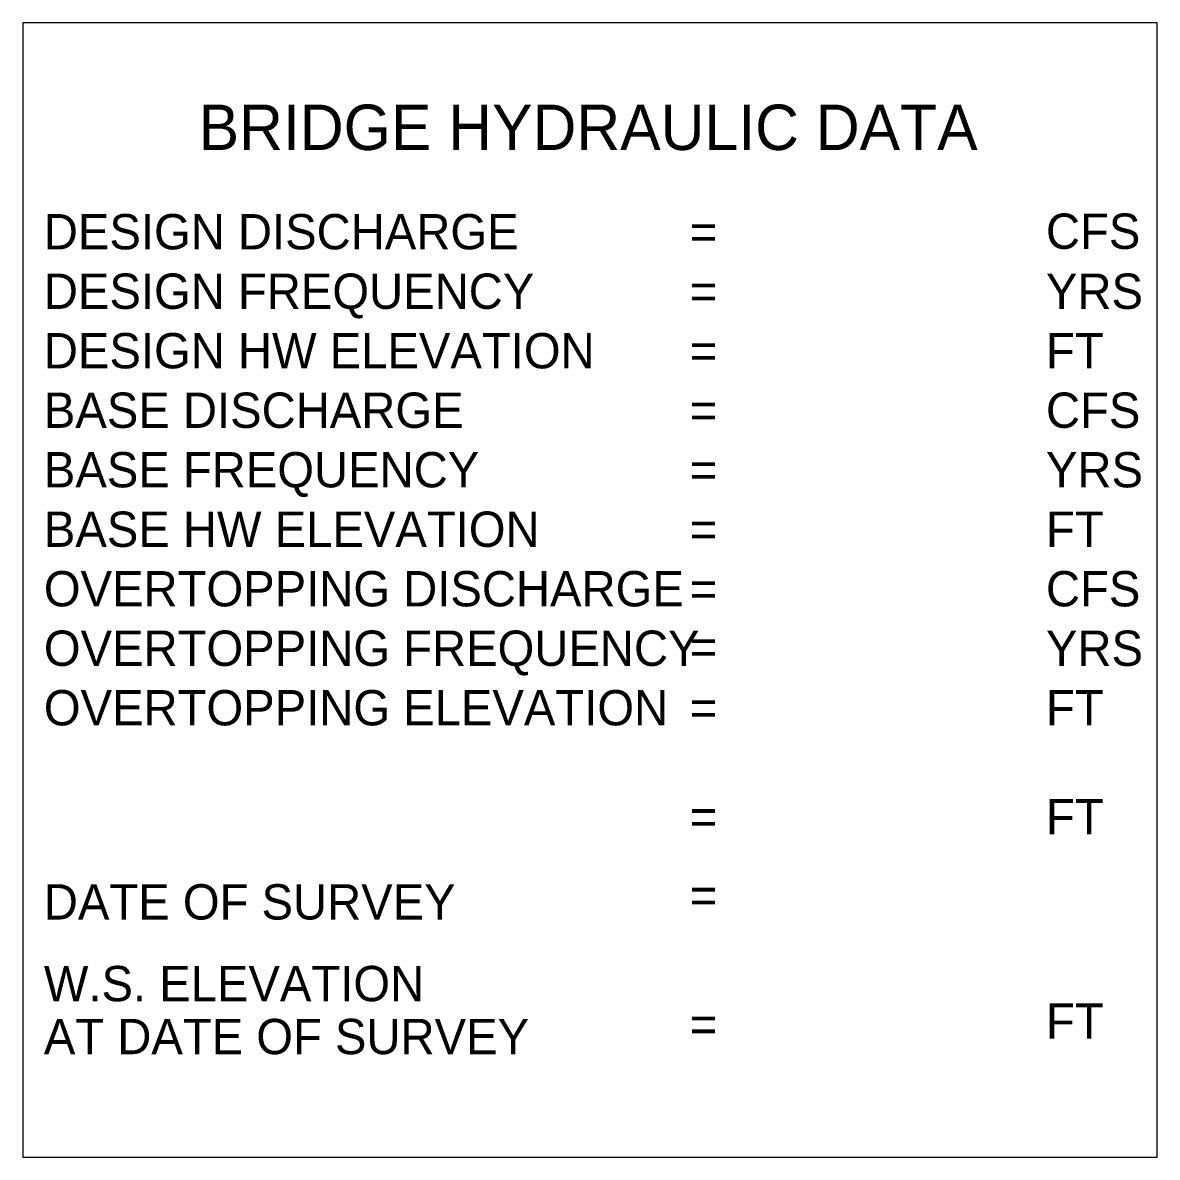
# Model space of a CAD drawing. Extents: x 1735444 to 1737729, y 696688 to 698970.
# Drawn here: x 1737339.8 to 1737564.8, y 696687.8 to 696912.8 of the extents above; entities that cross this region are included whole.
import ezdxf

# ---------------------------------------------------------------- set-up
doc = ezdxf.new("R2010")
doc.units = 0
doc.layers.add('Default', color=7, linetype='Continuous')
doc.layers.add('Prop Grid Mask', color=7, linetype='Continuous')

msp = doc.modelspace()

# ---------------------------------------------------------------- linework, layer by layer
at = {"layer": 'Prop Grid Mask'}
msp.add_lwpolyline([(1737339.83, 696687.8), (1737564.83, 696687.8), (1737564.83, 696912.8), (1737339.83, 696912.8)], close=True, dxfattribs=at)

# ---------------------------------------------------------------- texts
at = {"layer": 'Default'}
for s, height, p in [('BRIDGE HYDRAULIC DATA', 9, (1737374.73, 696887.55)), ('DESIGN DISCHARGE', 7, (1737344.03, 696867.85)), ('CFS', 7, (1737542.75, 696867.95)), ('=         ', 7, (1737472.1, 696867.85)), ('DESIGN FREQUENCY', 7, (1737344.03, 696856.05)), ('=    ', 7, (1737472.1, 696856.05)), ('YRS', 7, (1737542.75, 696856.05)), ('DESIGN HW ELEVATION', 7, (1737344.03, 696844.25)), ('FT', 7, (1737542.75, 696844.25)), ('=         ', 7, (1737472.1, 696844.25)), ('BASE DISCHARGE', 7, (1737344.03, 696832.45)), ('CFS', 7, (1737542.75, 696832.45)), ('=         ', 7, (1737472.1, 696832.45)), ('BASE FREQUENCY', 7, (1737344.03, 696820.65)), ('YRS', 7, (1737542.75, 696820.65)), ('=    ', 7, (1737472.1, 696820.65)), ('BASE HW ELEVATION', 7, (1737344.03, 696808.85)), ('=         ', 7, (1737472.1, 696808.85)), ('FT', 7, (1737542.75, 696808.85)), ('OVERTOPPING DISCHARGE', 7, (1737344.03, 696797.05)), ('CFS', 7, (1737542.75, 696797.05)), ('=         ', 7, (1737472.1, 696797.05)), ('OVERTOPPING FREQUENCY', 7, (1737344.03, 696785.25)), ('YRS', 7, (1737542.75, 696785.25)), ('=    ', 7, (1737472.1, 696785.54)), ('OVERTOPPING ELEVATION', 7, (1737344.03, 696773.45)), ('FT', 7, (1737542.75, 696773.45)), ('=         ', 7, (1737472.1, 696773.45)), ('FT', 7, (1737542.75, 696751.85)), ('=         ', 7, (1737472.1, 696751.85)), ('DATE OF SURVEY', 7, (1737344.03, 696734.95)), ('=           ', 7, (1737472.1, 696736.25)), ('W.S. ELEVATION', 7, (1737344.03, 696718.75)), ('FT', 7, (1737542.75, 696711.3)), ('AT DATE OF SURVEY', 7, (1737344.03, 696708.25)), ('=         ', 7, (1737472.1, 696710.7))]:
    msp.add_text(s, height=height, dxfattribs=at).set_placement(p)

doc.saveas('drawing.dxf')
